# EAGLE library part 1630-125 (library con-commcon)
COMPACT PCI TYPE B - 125 PINS 2mm HARD METRIC SOCKETS
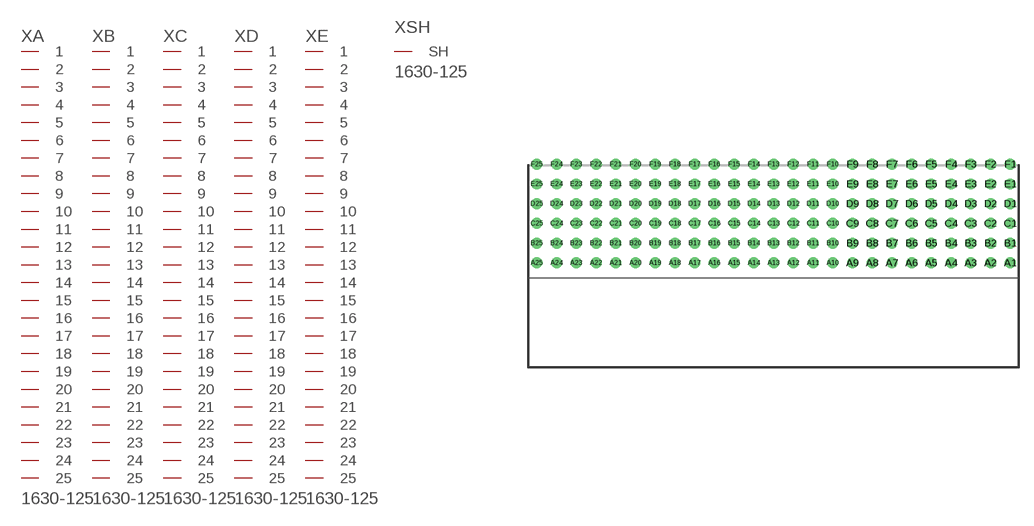
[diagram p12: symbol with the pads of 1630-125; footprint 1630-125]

Designator prefix X; gates A=PIN25 B=PIN25 C=PIN25 D=PIN25 E=PIN25 SH=SHIELD

## 1630-125 (OC_FARNELL: unknown; OC_NEWARK: unknown)  [1630-125]
A1  A:1  pas
A2  A:2  pas
A3  A:3  pas
A4  A:4  pas
A5  A:5  pas
A6  A:6  pas
A7  A:7  pas
A8  A:8  pas
A9  A:9  pas
A10  A:10  pas
A11  A:11  pas
A12  A:12  pas
A13  A:13  pas
A14  A:14  pas
A15  A:15  pas
A16  A:16  pas
A17  A:17  pas
A18  A:18  pas
A19  A:19  pas
A20  A:20  pas
A21  A:21  pas
A22  A:22  pas
A23  A:23  pas
A24  A:24  pas
A25  A:25  pas
B1  B:1  pas
B2  B:2  pas
B3  B:3  pas
B4  B:4  pas
B5  B:5  pas
B6  B:6  pas
B7  B:7  pas
B8  B:8  pas
B9  B:9  pas
B10  B:10  pas
B11  B:11  pas
B12  B:12  pas
B13  B:13  pas
B14  B:14  pas
B15  B:15  pas
B16  B:16  pas
B17  B:17  pas
B18  B:18  pas
B19  B:19  pas
B20  B:20  pas
B21  B:21  pas
B22  B:22  pas
B23  B:23  pas
B24  B:24  pas
B25  B:25  pas
C1  C:1  pas
C2  C:2  pas
C3  C:3  pas
C4  C:4  pas
C5  C:5  pas
C6  C:6  pas
C7  C:7  pas
C8  C:8  pas
C9  C:9  pas
C10  C:10  pas
C11  C:11  pas
C12  C:12  pas
C13  C:13  pas
C14  C:14  pas
C15  C:15  pas
C16  C:16  pas
C17  C:17  pas
C18  C:18  pas
C19  C:19  pas
C20  C:20  pas
C21  C:21  pas
C22  C:22  pas
C23  C:23  pas
C24  C:24  pas
C25  C:25  pas
D1  D:1  pas
D2  D:2  pas
D3  D:3  pas
D4  D:4  pas
D5  D:5  pas
D6  D:6  pas
D7  D:7  pas
D8  D:8  pas
D9  D:9  pas
D10  D:10  pas
D11  D:11  pas
D12  D:12  pas
D13  D:13  pas
D14  D:14  pas
D15  D:15  pas
D16  D:16  pas
D17  D:17  pas
D18  D:18  pas
D19  D:19  pas
D20  D:20  pas
D21  D:21  pas
D22  D:22  pas
D23  D:23  pas
D24  D:24  pas
D25  D:25  pas
E1  E:1  pas
E2  E:2  pas
E3  E:3  pas
E4  E:4  pas
E5  E:5  pas
E6  E:6  pas
E7  E:7  pas
E8  E:8  pas
E9  E:9  pas
E10  E:10  pas
E11  E:11  pas
E12  E:12  pas
E13  E:13  pas
E14  E:14  pas
E15  E:15  pas
E16  E:16  pas
E17  E:17  pas
E18  E:18  pas
E19  E:19  pas
E20  E:20  pas
E21  E:21  pas
E22  E:22  pas
E23  E:23  pas
E24  E:24  pas
E25  E:25  pas
F1  SH:SH  pas

## Footprint 1630-125 (pad centres in mm)
COMPACT PCI TYPE B - 125 PINS 2mm HARD METRIC SOCKETS
drill 0.6 round: A1 24,1.27; A2 22,1.27; A3 20,1.27; A4 18,1.27; A5 16,1.27; A6 14,1.27; A7 12,1.27; A8 10,1.27; A9 8,1.27; A10 6,1.27; A11 4,1.27; A12 2,1.27; A13 0,1.27; A14 -2,1.27; A15 -4,1.27; A16 -6,1.27; A17 -8,1.27; A18 -10,1.27; A19 -12,1.27; A20 -14,1.27; A21 -16,1.27; A22 -18,1.27; A23 -20,1.27; A24 -22,1.27; A25 -24,1.27; B1 24,3.27; B2 22,3.27; B3 20,3.27; B4 18,3.27; B5 16,3.27; B6 14,3.27; B7 12,3.27; B8 10,3.27; B9 8,3.27; B10 6,3.27; B11 4,3.27; B12 2,3.27; B13 0,3.27; B14 -2,3.27; B15 -4,3.27; B16 -6,3.27; B17 -8,3.27; B18 -10,3.27; B19 -12,3.27; B20 -14,3.27; B21 -16,3.27; B22 -18,3.27; B23 -20,3.27; B24 -22,3.27; B25 -24,3.27; C1 24,5.27; C2 22,5.27; C3 20,5.27; C4 18,5.27; C5 16,5.27; C6 14,5.27; C7 12,5.27; C8 10,5.27; C9 8,5.27; C10 6,5.27; C11 4,5.27; C12 2,5.27; C13 0,5.27; C14 -2,5.27; C15 -4,5.27; C16 -6,5.27; C17 -8,5.27; C18 -10,5.27; C19 -12,5.27; C20 -14,5.27; C21 -16,5.27; C22 -18,5.27; C23 -20,5.27; C24 -22,5.27; C25 -24,5.27; D1 24,7.27; D2 22,7.27; D3 20,7.27; D4 18,7.27; D5 16,7.27; D6 14,7.27; D7 12,7.27; D8 10,7.27; D9 8,7.27; D10 6,7.27; D11 4,7.27; D12 2,7.27; D13 0,7.27; D14 -2,7.27; D15 -4,7.27; D16 -6,7.27; D17 -8,7.27; D18 -10,7.27; D19 -12,7.27; D20 -14,7.27; D21 -16,7.27; D22 -18,7.27; D23 -20,7.27; D24 -22,7.27; D25 -24,7.27; E1 24,9.27; E2 22,9.27; E3 20,9.27; E4 18,9.27; E5 16,9.27; E6 14,9.27; E7 12,9.27; E8 10,9.27; E9 8,9.27; E10 6,9.27; E11 4,9.27; E12 2,9.27; E13 0,9.27; E14 -2,9.27; E15 -4,9.27; E16 -6,9.27; E17 -8,9.27; E18 -10,9.27; E19 -12,9.27; E20 -14,9.27; E21 -16,9.27; E22 -18,9.27; E23 -20,9.27; E24 -22,9.27; E25 -24,9.27; F1 24,11.27; F2 22,11.27; F3 20,11.27; F4 18,11.27; F5 16,11.27; F6 14,11.27; F7 12,11.27; F8 10,11.27; F9 8,11.27; F10 6,11.27; F11 4,11.27; F12 2,11.27; F13 0,11.27; F14 -2,11.27; F15 -4,11.27; F16 -6,11.27; F17 -8,11.27; F18 -10,11.27; F19 -12,11.27; F20 -14,11.27; F21 -16,11.27; F22 -18,11.27; F23 -20,11.27; F24 -22,11.27; F25 -24,11.27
